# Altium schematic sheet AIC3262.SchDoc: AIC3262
size 431 x 279 mm; Date: Not shown in title block; ApprovedBy: Not shown in title block; CheckedBy: Not shown in title block; Author: Not shown in title block; CompanyName: Not shown in title block; DrawnBy: LDN; Engineer: Not shown in title block; Organization: Not shown in title block; Address1: Not shown in title block; Address2: Not shown in title block; Address3: Not shown in title block; Address4: Not shown in title block; DocumentNumber: 1; Revision: Use project parameter SCH_Rev; SheetNumber: 4; SheetTotal: 13; PageSetup: Record=PageOptions¦CenterHorizontal=True¦CenterVertical=True¦PrintScale=1.00¦XCorrection=1.00¦YCorrection=1.00¦PrintKind=0¦BorderSize=5000000¦LeftOffset=0¦BottomOffset=0¦Orientation=2¦PaperLength=1000¦PaperWidth=1000¦Scale=100¦PaperSource=15¦PrintQuality=600¦MediaType=1¦DitherType=10¦PaperKind=Letter¦PrintScaleMode=1
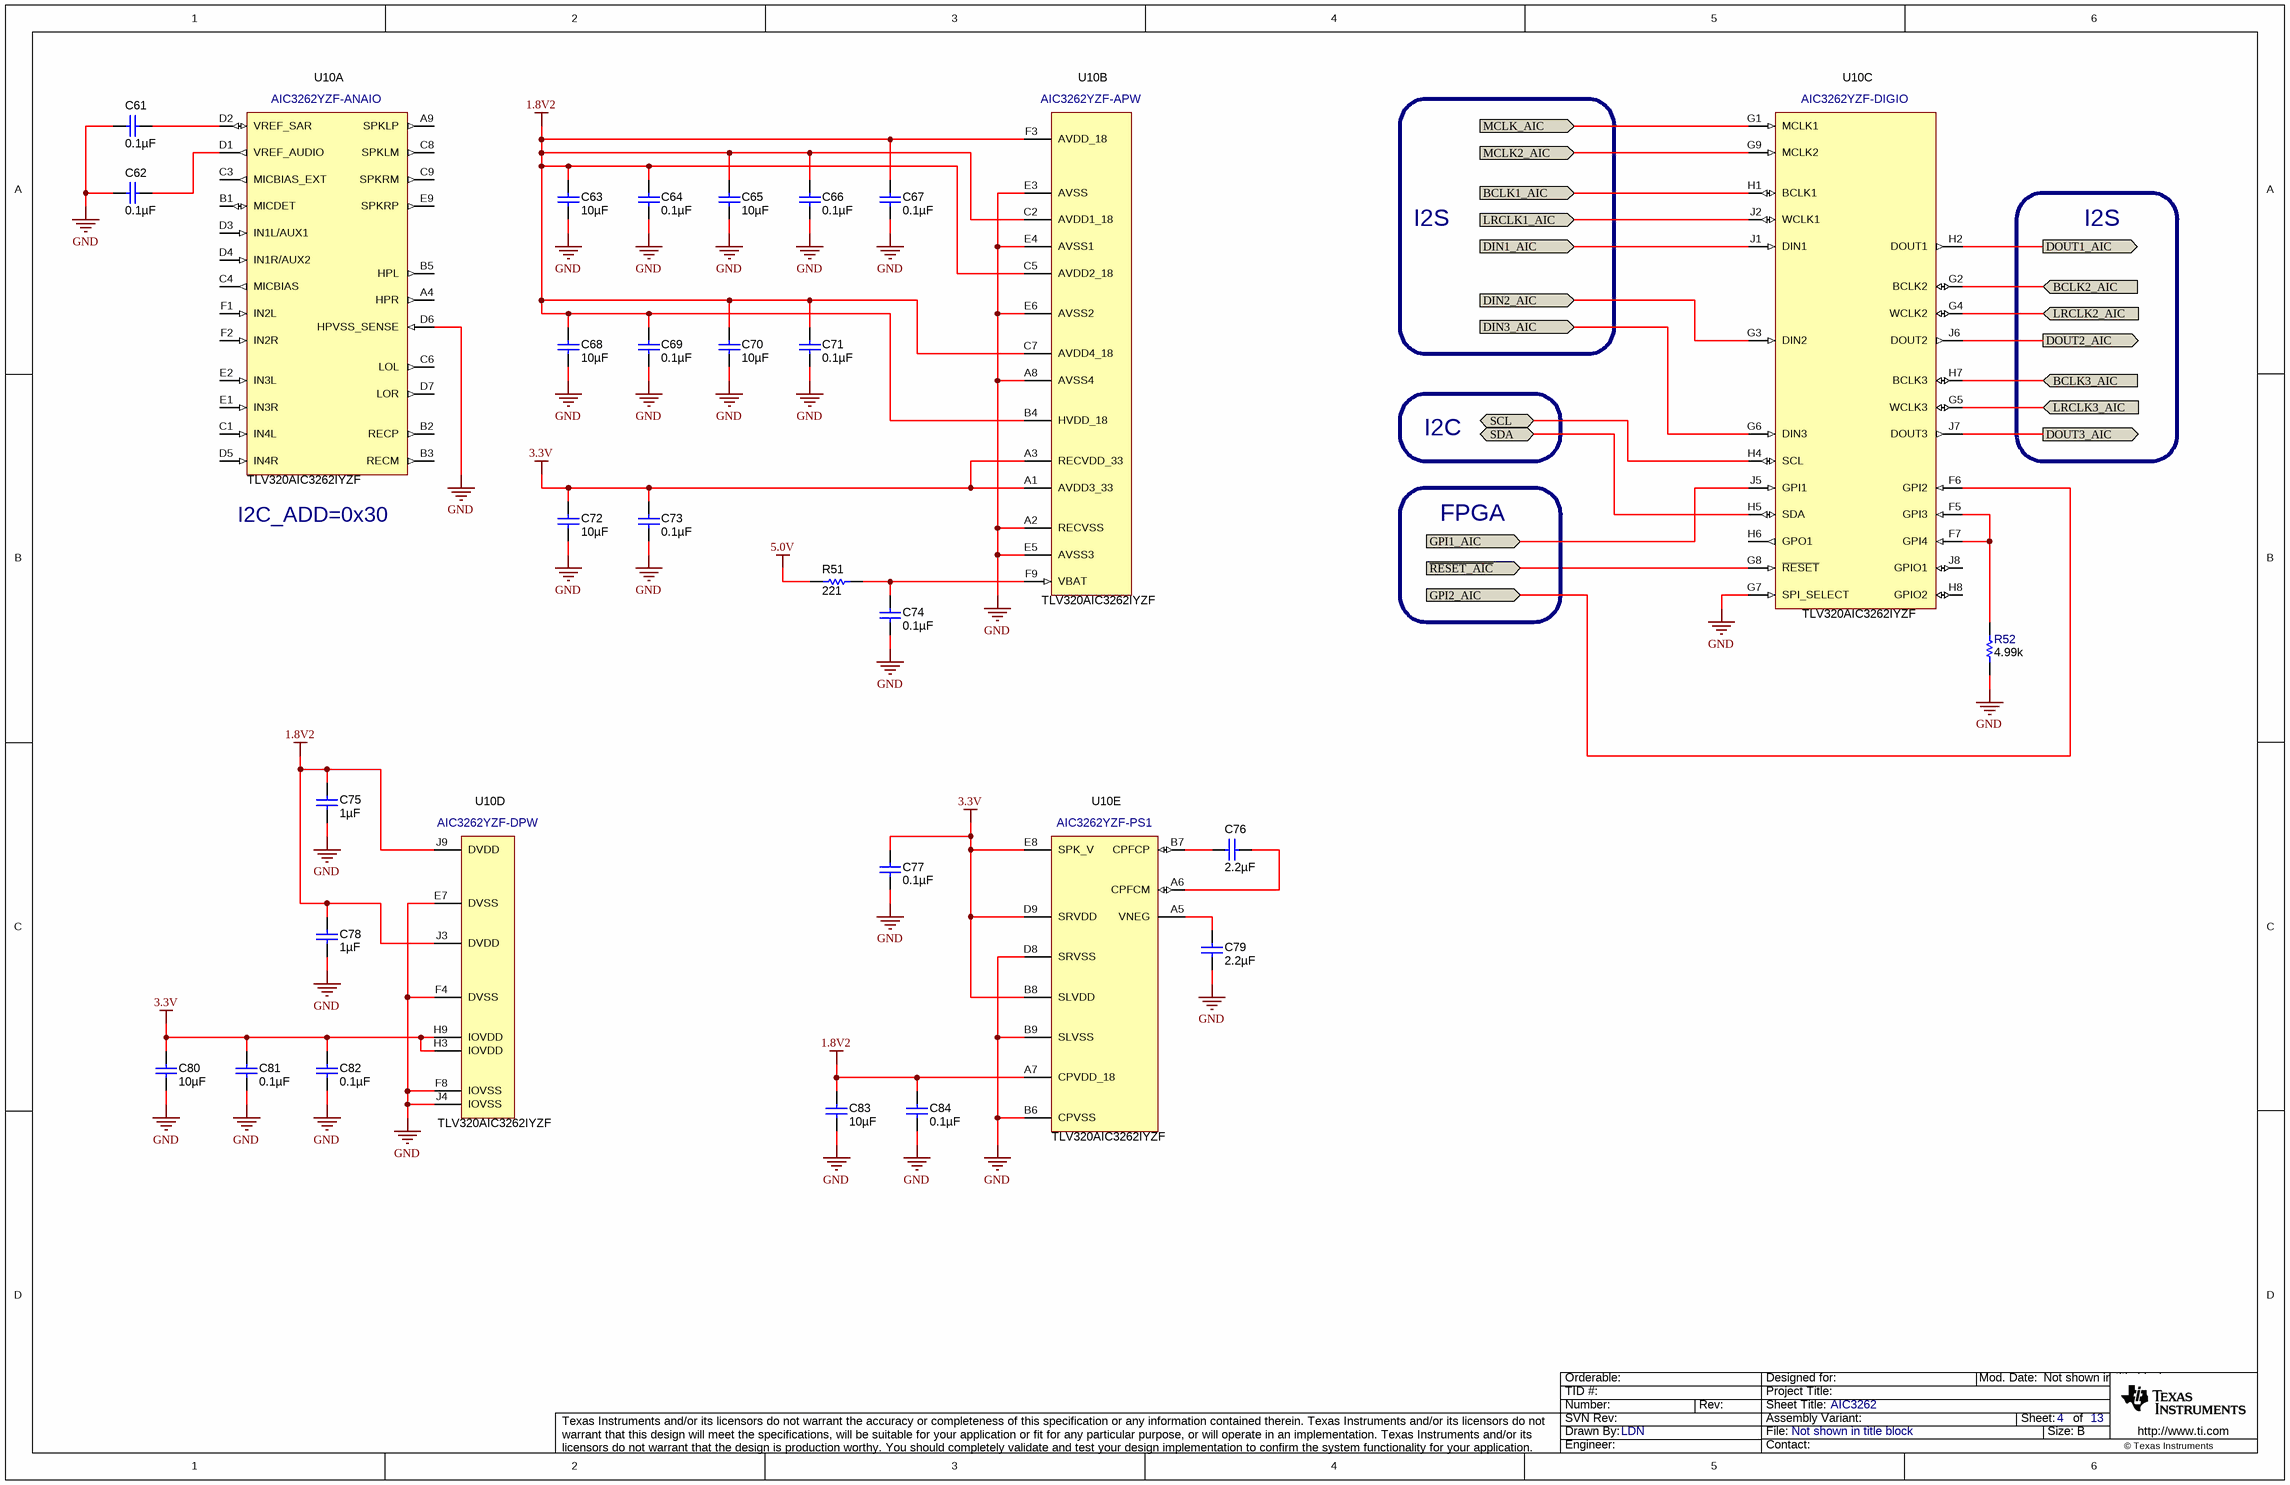
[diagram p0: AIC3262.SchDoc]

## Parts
C61  ValueDisplayed: 0.1µF  [0402]  (hidden comment: GRM155R71A104KA01D)
C62  ValueDisplayed: 0.1µF  [0402]  (hidden comment: GRM155R71A104KA01D)
C63  ValueDisplayed: 10µF  [0603L]  (hidden comment: GRM188R61A106ME69)
C64  ValueDisplayed: 0.1µF  [0402]  (hidden comment: GRM155R71A104KA01D)
C65  ValueDisplayed: 10µF  [0603L]  (hidden comment: GRM188R61A106ME69)
C66  ValueDisplayed: 0.1µF  [0402]  (hidden comment: GRM155R71A104KA01D)
C67  ValueDisplayed: 0.1µF  [0402]  (hidden comment: GRM155R71A104KA01D)
C68  ValueDisplayed: 10µF  [0603L]  (hidden comment: GRM188R61A106ME69)
C69  ValueDisplayed: 0.1µF  [0402]  (hidden comment: GRM155R71A104KA01D)
C70  ValueDisplayed: 10µF  [0603L]  (hidden comment: GRM188R61A106ME69)
C71  ValueDisplayed: 0.1µF  [0402]  (hidden comment: GRM155R71A104KA01D)
C72  ValueDisplayed: 10µF  [0603L]  (hidden comment: GRM188R61A106ME69)
C73  ValueDisplayed: 0.1µF  [0402]  (hidden comment: GRM155R71A104KA01D)
C74  ValueDisplayed: 0.1µF  [0402]  (hidden comment: GRM155R71A104KA01D)
C75  ValueDisplayed: 1µF  [0402L]  (hidden comment: GRM155R61A105KE15D)
C76  ValueDisplayed: 2.2µF  [0402L]  (hidden comment: C1005X5R1A225K050BC)
C77  ValueDisplayed: 0.1µF  [0402]  (hidden comment: GRM155R71A104KA01D)
C78  ValueDisplayed: 1µF  [0402L]  (hidden comment: GRM155R61A105KE15D)
C79  ValueDisplayed: 2.2µF  [0402L]  (hidden comment: C1005X5R1A225K050BC)
C80  ValueDisplayed: 10µF  [0603L]  (hidden comment: GRM188R61A106ME69)
C81  ValueDisplayed: 0.1µF  [0402]  (hidden comment: GRM155R71A104KA01D)
C82  ValueDisplayed: 0.1µF  [0402]  (hidden comment: GRM155R71A104KA01D)
C83  ValueDisplayed: 10µF  [0603L]  (hidden comment: GRM188R61A106ME69)
C84  ValueDisplayed: 0.1µF  [0402]  (hidden comment: GRM155R71A104KA01D)
R51  ValueDisplayed: 221  [0603L]  (hidden comment: CRCW0603221RFKEA)
R52  ValueDisplayed: 4.99k  [0402L]  (hidden comment: CRCW04024K99FKED)
U10  TLV320AIC3262IYZF  [YZF0081ATAT]  (parts A,B,C,D,E of 5)

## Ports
BCLK1_AIC (in), BCLK2_AIC (in), BCLK3_AIC (in), DIN1_AIC (in), DIN2_AIC (in), DIN3_AIC (in), DOUT1_AIC (out), DOUT2_AIC (out), DOUT3_AIC (out), GPI1_AIC (in), GPI2_AIC (in), LRCLK1_AIC (in), LRCLK2_AIC (in), LRCLK3_AIC (in), MCLK2_AIC (in), MCLK_AIC (in), SCL (bidir), SDA (bidir), ~{RESET_AIC} (in)

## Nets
1.8V2: C63.1 C64.1 C65.1 C66.1 C67.1 C68.1 C69.1 C70.1 C71.1 C75.1 C78.1 C83.1 C84.1 U10.A7(CPVDD_18) U10.B4(HVDD_18) U10.C2(AVDD1_18) U10.C5(AVDD2_18) U10.C7(AVDD4_18) U10.F3(AVDD_18) U10.J3(DVDD) U10.J9(DVDD)
3.3V: C72.1 C73.1 C77.1 C80.1 C81.1 C82.1 U10.A1(AVDD3_33) U10.A3(RECVDD_33) U10.B8(SLVDD) U10.D9(SRVDD) U10.E8(SPK_V) U10.H3(IOVDD) U10.H9(IOVDD)
5.0V: R51.1
GND: C61.1 C62.1 C63.2 C64.2 C65.2 C66.2 C67.2 C68.2 C69.2 C70.2 C71.2 C72.2 C73.2 C74.2 C75.2 C77.2 C78.2 C79.2 C80.2 C81.2 C82.2 C83.2 C84.2 R52.1 U10.A2(RECVSS) U10.A8(AVSS4) U10.B6(CPVSS) U10.B9(SLVSS) U10.D6(HPVSS_SENSE) U10.D8(SRVSS) U10.E3(AVSS) U10.E4(AVSS1) U10.E5(AVSS3) U10.E6(AVSS2) U10.E7(DVSS) U10.F4(DVSS) U10.F8(IOVSS) U10.G7(SPI_SELECT) U10.J4(IOVSS)
~{RESET_AIC}: U10.G8(~{RESET}) ; port ~{RESET_AIC}
BCLK1_AIC: U10.H1(BCLK1) ; port BCLK1_AIC
BCLK2_AIC: U10.G2(BCLK2) ; port BCLK2_AIC
BCLK3_AIC: U10.H7(BCLK3) ; port BCLK3_AIC
DIN1_AIC: U10.J1(DIN1) ; port DIN1_AIC
DIN2_AIC: U10.G3(DIN2) ; port DIN2_AIC
DIN3_AIC: U10.G6(DIN3) ; port DIN3_AIC
DOUT1_AIC: U10.H2(DOUT1) ; port DOUT1_AIC
DOUT2_AIC: U10.J6(DOUT2) ; port DOUT2_AIC
DOUT3_AIC: U10.J7(DOUT3) ; port DOUT3_AIC
GPI1_AIC: U10.J5(GPI1) ; port GPI1_AIC
GPI2_AIC: U10.F6(GPI2) ; port GPI2_AIC
LRCLK1_AIC: U10.J2(WCLK1) ; port LRCLK1_AIC
LRCLK2_AIC: U10.G4(WCLK2) ; port LRCLK2_AIC
LRCLK3_AIC: U10.G5(WCLK3) ; port LRCLK3_AIC
MCLK2_AIC: U10.G9(MCLK2) ; port MCLK2_AIC
MCLK_AIC: U10.G1(MCLK1) ; port MCLK_AIC
SCL: U10.H4(SCL) ; port SCL
SDA: U10.H5(SDA) ; port SDA
NetC61_2: C61.2 U10.D2(VREF_SAR)
NetC62_2: C62.2 U10.D1(VREF_AUDIO)
NetC74_1: C74.1 R51.2 U10.F9(VBAT)
NetC76_1: C76.1 U10.B7(CPFCP)
NetC76_2: C76.2 U10.A6(CPFCM)
NetC79_1: C79.1 U10.A5(VNEG)
NetR52_2: R52.2 U10.F5(GPI3) U10.F7(GPI4)

Not connected (* = marked no-connect by the designer): U10 A4(HPR) A9(SPKLP) B1(MICDET) B2(RECP) B3(RECM) B5(HPL) C1(IN4L) C3(MICBIAS_EXT) C4(MICBIAS) C6(LOL) C8(SPKLM) C9(SPKRM) D3(IN1L/AUX1) D4(IN1R/AUX2) D5(IN4R) D7(LOR) E1(IN3R) E2(IN3L) E9(SPKRP) F1(IN2L) F2(IN2R) H6(GPO1) H8(GPIO2) J8(GPIO1)

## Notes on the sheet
- I2S
- I2C
- (near U10) I2C_ADD=0x30
- FPGA

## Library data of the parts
C61 C62 C64 C66 C67 C69 C71 C73 C74 C77 C81 C82 C84 = GRM155R71A104KA01D: CAP, CERM, 0.1 µF, 10 V, +/- 10%, X7R, 0402; Manufacturer: MuRata; Polarized: N; CompType: Capacitor; Value: 0.1uF; U/M: EA; Cap_F: 0.0000001; Tolerance_%: 10; Value1: Unknown; Value2: 10V; TaMin_C: -55; TaMax_C: 125
C63 C65 C68 C70 C72 C80 C83 = GRM188R61A106ME69: CAP, CERM, 10 µF, 10 V, +/- 20%, X5R, 0603; Manufacturer: MuRata; Polarized: N; CompType: Capacitor; Value: 10uF; U/M: EA; Cap_F: 0.00001; Tolerance_%: 20; Value1: Unknown; VDC_V: 10; Value2: 10V; TaMin_C: -55; TaMax_C: 85; Cap_Case: 0603
C75 C78 = GRM155R61A105KE15D: CAP, CERM, 1 µF, 10 V, +/- 10%, X5R, 0402; Manufacturer: MuRata; Polarized: N; CompType: Capacitor; Value: 1uF; U/M: EA; Cap_F: 0.000001; Tolerance_%: 10; Value1: Unknown; Value2: 10V; TaMin_C: -55; TaMax_C: 85; Cap_Case: 0402
C76 C79 = C1005X5R1A225K050BC: CAP, CERM, 2.2 µF, 10 V, +/- 10%, X5R, 0402; Manufacturer: TDK; Polarized: N; CompType: Capacitor; Value: 2.2uF; U/M: EA; Cap_F: 0.0000022; Tolerance_%: 10; Value1: Unknown; Value2: 10V; TaMin_C: -55; TaMax_C: 85; Cap_Case: 0402
R51 = CRCW0603221RFKEA: RES, 221, 1%, 0.1 W, 0603; Manufacturer: Vishay-Dale; CompType: Resistor; Value: 221; Value_Code: 221R; Tolerance_%: 1; Power_W: 0.1; Value2: 0.1W; VDC_V: 75; TempCo: 100 ppm/C; EIA_Code: E96; U/M: EA
R52 = CRCW04024K99FKED: RES, 4.99 k, 1%, 0.063 W, 0402; Manufacturer: Vishay-Dale; CompType: Resistor; Value: 4.99k; Res_ohm: 4990; Value_Code: 4k99; Tolerance_%: 1; Power_W: 0.063; Value2: 0.063W; VDC_V: 50; TempCo: 100 ppm/C; EIA_Code: E96; U/M: EA
U10 = TLV320AIC3262IYZF: Ultra Low Power Stereo Audio Codec With miniDSP, DirectPath Headphone, and Stereo Class-Dspeaker Amplifier, YZF0081ATAT; Manufacturer: Texas Instruments; SymbolCreator: x0208326; CompType: IC; U/M: EA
